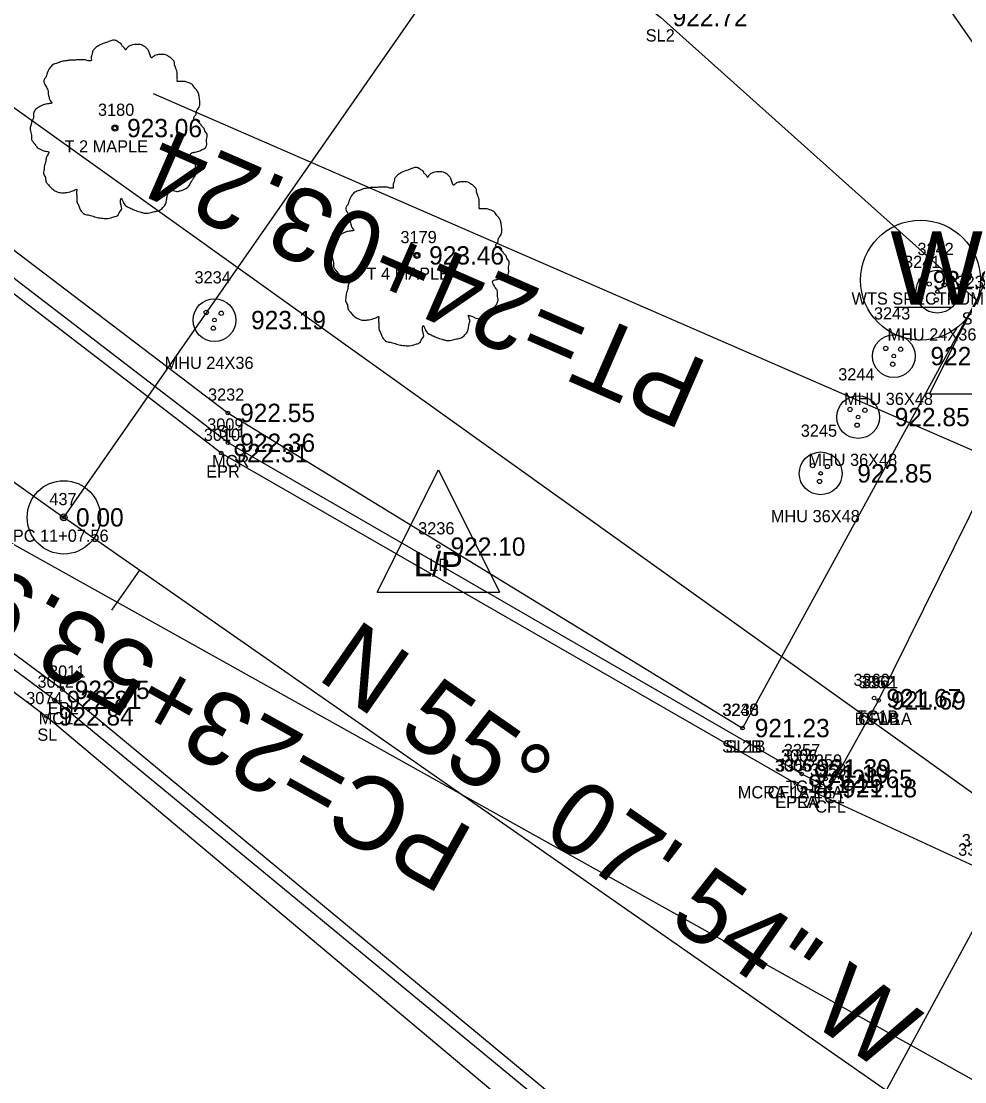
# Model space of a CAD drawing. Extents: x 1575382 to 1578175, y 1099175 to 1101955.
# Drawn here: x 1576997.2 to 1577074.4, y 1100781 to 1100867.9 of the extents above; entities that cross this region are included whole.
import ezdxf

# ---------------------------------------------------------------- set-up
doc = ezdxf.new("R2010")
doc.units = 0
for name, color, linetype in [('RD_EX_Conc', 7, 'Continuous'), ('RD_EX_Conc_txCode', 7, 'Continuous'), ('RD_EX_DR_Inlet', 7, 'Continuous'), ('RD_EX_DR_Pipe', 7, 'Continuous'), ('RD_EX_Road', 7, 'Continuous'), ('RD_EX_Road_txCode', 7, 'Continuous'), ('RD_EX_TX_Conc_ELEV', 7, 'Continuous'), ('RD_EX_TX_Road_ELEV', 7, 'Continuous'), ('RD_EX_TX_UT_ELEV', 7, 'Continuous'), ('RD_EX_TX_VEG_ELEV', 7, 'Continuous'), ('RD_EX_UT', 7, 'Continuous'), ('RD_EX_UT_txCode', 7, 'Continuous'), ('RD_EX_VEG', 7, 'Continuous'), ('RD_EX_VEG_txCode', 7, 'Continuous'), ('RD_HC_Cl', 7, 'Continuous'), ('RD_HC_Data', 7, 'Continuous'), ('RD_HC_Data_Tic', 7, 'Continuous'), ('RD_HC_Survey_ELEV', 7, 'Continuous'), ('RD_HC_txCode', 7, 'Continuous'), ('RD_SMD_Locator', 7, 'Continuous')]:
    doc.layers.add(name, color=color, linetype=linetype)

msp = doc.modelspace()

# ---------------------------------------------------------------- linework, layer by layer
at = {"layer": 'RD_EX_Conc'}
for points in [[(1577061.066, 1100806.234), (1577014.096, 1100833.352), (1576975.058, 1100863.303), (1576939.512, 1100897.242), (1576908.218, 1100933.822), (1576881.099, 1100974.578), (1576859.041, 1101017.292), (1576841.041, 1101063.527), (1576828.933, 1101110.765), (1576816.791, 1101158.901)], [(1577043.777, 1100776.098), (1576999.879, 1100812.296), (1576959.091, 1100842.628), (1576920.948, 1100878.726), (1576886.666, 1100919.361), (1576858.724, 1100961.136), (1576834.43, 1101008.647), (1576816.373, 1101055.231), (1576803.494, 1101104.71), (1576791.52, 1101152.573)], [(1577067.37, 1100812.254), (1577083.485, 1100844.878), (1577096.643, 1100874.508), (1577116.651, 1100919.942), (1577136.82, 1100965.443), (1577156.654, 1101010.405), (1577183.297, 1101070.643)], [(1577061.066, 1100806.234), (1577063.378, 1100805.064), (1577067.37, 1100812.254)]]:
    msp.add_lwpolyline(points, dxfattribs=at)
at = {"layer": 'RD_EX_DR_Inlet'}
for centre, radius in [((1577072.173, 1100845.722), 1.75), ((1577071.508, 1100846.352), 0.175), ((1577072.733, 1100846.282), 0.175), ((1577012.98, 1100843.399), 1.75), ((1577072.085, 1100845.058), 0.175), ((1577012.315, 1100844.029), 0.175), ((1577013.54, 1100843.959), 0.175), ((1577012.893, 1100842.734), 0.175), ((1577068.613, 1100840.447), 1.75), ((1577067.948, 1100841.076), 0.175), ((1577069.173, 1100841.007), 0.175), ((1577068.525, 1100839.782), 0.175), ((1577065.687, 1100835.457), 1.75), ((1577065.023, 1100836.086), 0.175), ((1577066.247, 1100836.017), 0.175), ((1577065.6, 1100834.792), 0.175), ((1577062.621, 1100830.846), 1.75), ((1577061.956, 1100831.476), 0.175), ((1577063.18, 1100831.406), 0.175), ((1577062.533, 1100830.181), 0.175)]:
    msp.add_circle(centre, radius, dxfattribs=at)
at = {"layer": 'RD_EX_DR_Pipe'}
msp.add_line((1577132.688, 1100782.794), (1577050.186, 1100902.125), dxfattribs=at)
at = {"layer": 'RD_EX_Road'}
for points in [[(1577060.606, 1100805.432), (1577013.537, 1100832.507), (1576974.41, 1100862.521), (1576938.821, 1100896.441), (1576907.275, 1100933.28), (1576880.287, 1100973.975), (1576858.202, 1101016.828), (1576840.123, 1101063.131), (1576827.927, 1101110.583), (1576815.842, 1101158.489)], [(1577060.606, 1100805.432), (1577075.531, 1100798.536), (1577081.931, 1100797.671), (1577087.923, 1100798.374), (1577091.212, 1100799.398), (1577094.487, 1100804.268), (1577106.896, 1100832.158), (1577119.895, 1100862.619), (1577139.857, 1100909.397), (1577159.206, 1100954.774), (1577178.498, 1100999.731), (1577192.432, 1101032.313), (1577206.431, 1101064.716)], [(1576898.125, 1100449.597), (1576900.298, 1100453.323), (1576908.44, 1100470.191), (1576911.626, 1100476.811), (1576915.143, 1100482.86), (1576932.491, 1100514.031), (1576964.319, 1100571.231), (1576981.085, 1100601.291), (1577005.143, 1100644.548), (1577029.514, 1100688.699), (1577055.929, 1100735.941), (1577058.213, 1100744.654), (1577059.154, 1100754.07), (1577057.45, 1100760.722), (1577053.131, 1100767.877), (1577044.533, 1100776.687), (1577044.533, 1100776.687), (1577000.541, 1100813.123), (1576959.676, 1100843.401), (1576921.642, 1100879.474), (1576887.689, 1100919.798), (1576859.542, 1100961.835), (1576835.397, 1101008.919), (1576817.257, 1101055.711)]]:
    msp.add_lwpolyline(points, dxfattribs=at)
at = {"layer": 'RD_EX_UT'}
for p, q in [((1577071.545, 1100837.363), (1577076.545, 1100847.363)), ((1577068.665, 1100844.456), (1577073.295, 1100844.456)), ((1577071.545, 1100837.363), (1577081.545, 1100837.363)), ((1577026.316, 1100821.125), (1577031.316, 1100831.125)), ((1577031.316, 1100831.125), (1577036.316, 1100821.125)), ((1577026.316, 1100821.125), (1577036.316, 1100821.125))]:
    msp.add_line(p, q, dxfattribs=at)
msp.add_lwpolyline([(1576697.982, 1101074.318), (1577079.486, 1100801.524), (1576931.929, 1100529.296), (1577183.503, 1100413.666)], dxfattribs=at)
msp.add_circle((1577070.794, 1100846.664), 4.908, dxfattribs=at)
at = {"layer": 'RD_EX_VEG'}
for points in [[(1576842.661, 1101165.203), (1576856.324, 1101117.296), (1576901.07, 1101050.702), (1576926.345, 1101005.763), (1576957.585, 1100975.469), (1576985.787, 1100943.994), (1577005.951, 1100901.315), (1577049.501, 1100868.209), (1577075.374, 1100845.032), (1577056.225, 1100809.989)], [(1576823.907, 1101161.244), (1576835.181, 1101111.009), (1576847.368, 1101072.746), (1576888.665, 1101041.707), (1576913.762, 1100995.867), (1576945.147, 1100967.302), (1576973.299, 1100933.425), (1576973.63, 1100896.298), (1576975.024, 1100865.506), (1577014.084, 1100835.799), (1577056.225, 1100809.989)], [(1576815.034, 1101055.099), (1576833.721, 1101006.581), (1576857.566, 1100960.375), (1576886.692, 1100916.883), (1576920.078, 1100877.681), (1576958.628, 1100841.518), (1576999.237, 1100810.946), (1577044.614, 1100772.82), (1577027.667, 1100742.339), (1577009.85, 1100750.508), (1576988.317, 1100759.291), (1576965.743, 1100773.629), (1576933.976, 1100810.235), (1576917.815, 1100828.049), (1576903.899, 1100864.233), (1576883.403, 1100895.406), (1576864.834, 1100917.249), (1576817.517, 1100956.766)]]:
    msp.add_lwpolyline(points, dxfattribs=at)
for centre, radius in [((1577004.83, 1100859.122), 0.25), ((1577004.818, 1100859.103), 0.0001), ((1577029.559, 1100848.695), 0.25), ((1577029.546, 1100848.676), 0.0001)]:
    msp.add_circle(centre, radius, dxfattribs=at)
for points in [[(1577004.962, 1100866.289), (1577004.662, 1100866.314), (1577004.338, 1100866.214), (1577004.088, 1100866.114), (1577003.863, 1100866.039), (1577003.638, 1100865.939), (1577003.338, 1100865.764), (1577003.113, 1100865.564), (1577002.988, 1100865.314), (1577002.938, 1100865.089), (1577002.888, 1100864.814), (1577002.888, 1100864.639), (1577002.763, 1100864.614), (1577002.613, 1100864.639), (1577002.363, 1100864.714), (1577002.113, 1100864.714), (1577001.864, 1100864.714), (1577001.514, 1100864.689), (1577001.164, 1100864.689), (1577000.889, 1100864.639), (1577000.564, 1100864.59), (1577000.189, 1100864.465), (1576999.839, 1100864.34), (1576999.54, 1100864.09), (1576999.29, 1100863.615), (1576999.165, 1100863.265), (1576999.015, 1100863.015), (1576999.165, 1100862.565), (1576999.34, 1100862.215), (1576999.365, 1100862.016), (1576999.44, 1100861.591), (1576999.54, 1100861.366), (1576999.665, 1100861.166), (1576999.59, 1100861.141), (1576999.215, 1100861.091), (1576998.915, 1100860.991), (1576998.49, 1100860.766), (1576998.265, 1100860.541), (1576998.165, 1100860.216), (1576998.14, 1100859.867), (1576998.04, 1100859.667), (1576997.965, 1100859.392), (1576997.94, 1100859.317), (1576997.89, 1100858.992), (1576997.99, 1100858.542), (1576998.015, 1100858.192), (1576998.14, 1100857.967), (1576998.29, 1100857.792), (1576998.465, 1100857.543), (1576998.865, 1100857.318), (1576999.19, 1100857.218), (1576999.39, 1100857.193), (1576999.215, 1100856.693), (1576999.165, 1100856.343), (1576999.04, 1100855.943), (1576999.04, 1100855.868), (1576998.99, 1100855.394), (1576999.14, 1100855.069), (1576999.215, 1100854.694), (1576999.39, 1100854.469), (1576999.665, 1100854.169), (1576999.989, 1100853.944), (1577000.489, 1100853.819), (1577000.889, 1100853.844), (1577001.464, 1100854.019), (1577001.714, 1100854.094), (1577001.689, 1100853.919), (1577001.714, 1100853.544), (1577001.714, 1100853.12), (1577001.864, 1100852.795), (1577001.964, 1100852.52), (1577002.113, 1100852.27), (1577002.438, 1100852.045), (1577002.838, 1100851.97), (1577003.263, 1100851.82), (1577003.713, 1100851.745), (1577004.213, 1100851.72), (1577004.812, 1100851.87), (1577005.087, 1100851.995), (1577005.187, 1100852.17), (1577005.387, 1100852.545), (1577005.337, 1100852.77), (1577005.362, 1100853.369), (1577005.462, 1100853.194), (1577005.637, 1100852.845), (1577006.137, 1100852.545), (1577006.537, 1100852.37), (1577007.011, 1100852.22), (1577007.311, 1100852.145), (1577007.786, 1100852.22), (1577008.161, 1100852.295), (1577008.536, 1100852.42), (1577008.836, 1100852.695), (1577009.01, 1100852.97), (1577009.06, 1100853.244), (1577009.135, 1100853.619), (1577009.185, 1100853.794)], [(1577009.185, 1100853.794), (1577009.11, 1100853.969), (1577009.06, 1100854.219), (1577009.135, 1100854.194), (1577009.31, 1100854.144), (1577009.585, 1100854.019), (1577009.81, 1100853.944), (1577010.135, 1100853.969), (1577010.41, 1100854.069), (1577010.86, 1100854.344), (1577011.135, 1100854.819), (1577011.409, 1100855.219), (1577011.484, 1100855.543), (1577011.434, 1100855.768), (1577011.409, 1100856.268), (1577011.209, 1100856.518), (1577011.159, 1100856.643), (1577011.06, 1100857.043), (1577011.135, 1100857.093), (1577011.409, 1100857.143), (1577011.784, 1100857.268), (1577012.059, 1100857.393), (1577012.284, 1100857.568), (1577012.359, 1100857.792), (1577012.334, 1100858.192), (1577012.384, 1100858.592), (1577012.309, 1100858.742), (1577012.209, 1100858.892), (1577012.134, 1100859.092), (1577011.984, 1100859.242), (1577011.884, 1100859.392), (1577011.784, 1100859.492), (1577011.659, 1100859.642), (1577011.484, 1100859.767), (1577011.334, 1100859.817), (1577011.284, 1100859.967), (1577011.434, 1100860.166), (1577011.484, 1100860.266), (1577011.509, 1100860.491), (1577011.734, 1100860.841), (1577011.784, 1100861.241), (1577011.734, 1100861.666), (1577011.684, 1100861.941), (1577011.534, 1100862.215), (1577011.334, 1100862.465), (1577011.209, 1100862.64), (1577011.035, 1100862.765), (1577010.71, 1100862.89), (1577010.46, 1100862.94), (1577010.11, 1100862.94), (1577009.91, 1100862.99), (1577009.935, 1100863.04), (1577009.935, 1100863.19), (1577009.935, 1100863.465), (1577009.86, 1100863.915), (1577009.71, 1100864.415), (1577009.71, 1100864.44), (1577009.61, 1100864.689), (1577009.385, 1100864.889), (1577009.21, 1100864.989), (1577009.01, 1100865.114), (1577008.761, 1100865.139), (1577008.461, 1100865.139), (1577008.186, 1100865.089), (1577007.986, 1100864.989), (1577007.811, 1100864.864), (1577007.736, 1100865.014), (1577007.636, 1100865.314), (1577007.586, 1100865.464), (1577007.436, 1100865.639), (1577007.211, 1100865.839), (1577006.761, 1100865.964), (1577006.137, 1100865.889), (1577005.837, 1100865.689), (1577005.687, 1100865.514), (1577005.637, 1100865.639), (1577005.437, 1100865.839), (1577005.337, 1100866.014), (1577005.162, 1100866.139), (1577005.012, 1100866.239), (1577004.912, 1100866.289)], [(1577029.691, 1100855.862), (1577029.391, 1100855.887), (1577029.066, 1100855.787), (1577028.816, 1100855.687), (1577028.591, 1100855.612), (1577028.366, 1100855.512), (1577028.066, 1100855.337), (1577027.841, 1100855.137), (1577027.716, 1100854.887), (1577027.666, 1100854.663), (1577027.616, 1100854.388), (1577027.616, 1100854.213), (1577027.492, 1100854.188), (1577027.342, 1100854.213), (1577027.092, 1100854.288), (1577026.842, 1100854.288), (1577026.592, 1100854.288), (1577026.242, 1100854.263), (1577025.892, 1100854.263), (1577025.617, 1100854.213), (1577025.292, 1100854.163), (1577024.918, 1100854.038), (1577024.568, 1100853.913), (1577024.268, 1100853.663), (1577024.018, 1100853.188), (1577023.893, 1100852.838), (1577023.743, 1100852.588), (1577023.893, 1100852.139), (1577024.068, 1100851.789), (1577024.093, 1100851.589), (1577024.168, 1100851.164), (1577024.268, 1100850.939), (1577024.393, 1100850.739), (1577024.318, 1100850.714), (1577023.943, 1100850.664), (1577023.643, 1100850.564), (1577023.218, 1100850.339), (1577022.993, 1100850.115), (1577022.893, 1100849.79), (1577022.869, 1100849.44), (1577022.769, 1100849.24), (1577022.694, 1100848.965), (1577022.669, 1100848.89), (1577022.619, 1100848.565), (1577022.719, 1100848.115), (1577022.744, 1100847.766), (1577022.869, 1100847.541), (1577023.018, 1100847.366), (1577023.193, 1100847.116), (1577023.593, 1100846.891), (1577023.918, 1100846.791), (1577024.118, 1100846.766), (1577023.943, 1100846.266), (1577023.893, 1100845.916), (1577023.768, 1100845.517), (1577023.768, 1100845.442), (1577023.718, 1100844.967), (1577023.868, 1100844.642), (1577023.943, 1100844.267), (1577024.118, 1100844.042), (1577024.393, 1100843.742), (1577024.718, 1100843.517), (1577025.218, 1100843.392), (1577025.617, 1100843.417), (1577026.192, 1100843.592), (1577026.442, 1100843.667), (1577026.417, 1100843.492), (1577026.442, 1100843.118), (1577026.442, 1100842.693), (1577026.592, 1100842.368), (1577026.692, 1100842.093), (1577026.842, 1100841.843), (1577027.167, 1100841.618), (1577027.566, 1100841.543), (1577027.991, 1100841.393), (1577028.441, 1100841.318), (1577028.941, 1100841.293), (1577029.541, 1100841.443), (1577029.815, 1100841.568), (1577029.915, 1100841.743), (1577030.115, 1100842.118), (1577030.065, 1100842.343), (1577030.09, 1100842.943), (1577030.19, 1100842.768), (1577030.365, 1100842.418), (1577030.865, 1100842.118), (1577031.265, 1100841.943), (1577031.74, 1100841.793), (1577032.04, 1100841.718), (1577032.514, 1100841.793), (1577032.889, 1100841.868), (1577033.264, 1100841.993), (1577033.564, 1100842.268), (1577033.739, 1100842.543), (1577033.789, 1100842.818), (1577033.864, 1100843.193), (1577033.914, 1100843.367)], [(1577033.914, 1100843.367), (1577033.839, 1100843.542), (1577033.789, 1100843.792), (1577033.864, 1100843.767), (1577034.039, 1100843.717), (1577034.314, 1100843.592), (1577034.538, 1100843.517), (1577034.863, 1100843.542), (1577035.138, 1100843.642), (1577035.588, 1100843.917), (1577035.863, 1100844.392), (1577036.138, 1100844.792), (1577036.213, 1100845.117), (1577036.163, 1100845.342), (1577036.138, 1100845.841), (1577035.938, 1100846.091), (1577035.888, 1100846.216), (1577035.788, 1100846.616), (1577035.863, 1100846.666), (1577036.138, 1100846.716), (1577036.513, 1100846.841), (1577036.787, 1100846.966), (1577037.012, 1100847.141), (1577037.087, 1100847.366), (1577037.062, 1100847.766), (1577037.112, 1100848.165), (1577037.037, 1100848.315), (1577036.937, 1100848.465), (1577036.862, 1100848.665), (1577036.712, 1100848.815), (1577036.613, 1100848.965), (1577036.513, 1100849.065), (1577036.388, 1100849.215), (1577036.213, 1100849.34), (1577036.063, 1100849.39), (1577036.013, 1100849.54), (1577036.163, 1100849.74), (1577036.213, 1100849.84), (1577036.238, 1100850.065), (1577036.463, 1100850.414), (1577036.513, 1100850.814), (1577036.463, 1100851.239), (1577036.413, 1100851.514), (1577036.263, 1100851.789), (1577036.063, 1100852.039), (1577035.938, 1100852.214), (1577035.763, 1100852.339), (1577035.438, 1100852.464), (1577035.188, 1100852.513), (1577034.838, 1100852.513), (1577034.638, 1100852.563), (1577034.663, 1100852.613), (1577034.663, 1100852.763), (1577034.663, 1100853.038), (1577034.588, 1100853.488), (1577034.438, 1100853.988), (1577034.438, 1100854.013), (1577034.338, 1100854.263), (1577034.114, 1100854.463), (1577033.939, 1100854.563), (1577033.739, 1100854.688), (1577033.489, 1100854.713), (1577033.189, 1100854.713), (1577032.914, 1100854.663), (1577032.714, 1100854.563), (1577032.539, 1100854.438), (1577032.464, 1100854.588), (1577032.364, 1100854.887), (1577032.314, 1100855.037), (1577032.164, 1100855.212), (1577031.94, 1100855.412), (1577031.49, 1100855.537), (1577030.865, 1100855.462), (1577030.565, 1100855.262), (1577030.415, 1100855.087), (1577030.365, 1100855.212), (1577030.165, 1100855.412), (1577030.065, 1100855.587), (1577029.89, 1100855.712), (1577029.741, 1100855.812), (1577029.641, 1100855.862)]]:
    msp.add_spline(points, degree=3, dxfattribs=at)
at = {"layer": 'RD_HC_Cl'}
msp.add_line((1577088.898, 1100765.75), (1577000.647, 1100827.242), dxfattribs=at)
msp.add_arc((1577257.909, 1101196.452), 450, 194.10128, 235.13175, dxfattribs=at)
at = {"layer": 'RD_HC_Data'}
for p, q in [((1577000.647, 1100827.242), (1577067.498, 1100923.183)), ((1577114.032, 1100815.757), (1577007.98, 1100861.919)), ((1577092.181, 1100771.631), (1576990.287, 1100828.5))]:
    msp.add_line(p, q, dxfattribs=at)
for radius in [3, 0.282]:
    msp.add_circle((1577000.647, 1100827.242), radius, dxfattribs=at)
at = {"layer": 'RD_HC_Data_Tic'}
msp.add_line((1577006.851, 1100822.919), (1577004.565, 1100819.637), dxfattribs=at)
at = {"layer": 'RD_SMD_Locator'}
for centre in [(1577004.83, 1100859.121), (1577029.559, 1100848.695), (1577070.794, 1100846.664), (1577072.173, 1100845.722), (1577012.98, 1100843.399), (1577068.613, 1100840.447), (1577014.084, 1100835.799), (1577065.687, 1100835.457), (1577014.096, 1100833.352), (1577013.537, 1100832.507), (1577062.621, 1100830.846), (1577000.647, 1100827.242), (1577031.316, 1100824.85), (1576999.879, 1100812.296), (1577000.541, 1100813.123), (1577067, 1100812.439), (1577067.37, 1100812.254), (1577067.37, 1100812.254), (1576999.237, 1100810.946), (1577056.225, 1100809.989), (1577056.225, 1100809.989), (1577061.066, 1100806.234), (1577061.066, 1100806.234), (1577061.237, 1100806.69), (1577060.606, 1100805.432), (1577060.606, 1100805.432), (1577063.034, 1100805.832), (1577063.378, 1100805.064)]:
    msp.add_circle(centre, 0.15, dxfattribs=at)

# ---------------------------------------------------------------- texts
at = {"layer": 'RD_EX_Conc_txCode'}
for s, p in [('3009', (1577012.388, 1100834.352)), ('MCR', (1577012.781, 1100831.352)), ('3012', (1576998.493, 1100813.296)), ('3360', (1577065.307, 1100813.439)), ('3362', (1577065.717, 1100813.254)), ('3361', (1577066, 1100813.254)), ('MCL', (1576998.587, 1100810.296)), ('BSW1A', (1577065.402, 1100810.254)), ('TC1B', (1577065.567, 1100810.439)), ('CFLB', (1577065.693, 1100810.254)), ('3005', (1577059.357, 1100807.234)), ('3356', (1577059.412, 1100807.234)), ('3357', (1577059.607, 1100807.69)), ('3359', (1577061.404, 1100806.832)), ('3358', (1577061.748, 1100806.064)), ('TC1A', (1577059.788, 1100804.69)), ('MCRA 12 FLAT', (1577055.838, 1100804.234)), ('CFLA 18', (1577058.271, 1100804.234)), ('TC1', (1577062.074, 1100803.832)), ('CFL', (1577062.173, 1100803.064)), ('3367', (1577074.183, 1100800.311))]:
    msp.add_text(s, height=1, dxfattribs=at).set_placement(p)
at = {"layer": 'RD_EX_Road_txCode'}
for s, p in [('3010', (1577012.112, 1100833.507)), ('EPR', (1577012.309, 1100830.507)), ('3011', (1576999.438, 1100814.123)), ('EPL', (1576999.336, 1100811.123)), ('3006', (1577058.874, 1100806.432)), ('3355', (1577058.976, 1100806.432)), ('EPRA', (1577058.889, 1100803.432)), ('EPLA', (1577058.913, 1100803.432)), ('3368', (1577073.878, 1100799.536))]:
    msp.add_text(s, height=1, dxfattribs=at).set_placement(p)
at = {"layer": 'RD_EX_TX_Conc_ELEV'}
for s, p in [('922.36', (1577015.096, 1100832.602)), ('922.81', (1577000.879, 1100811.546)), ('921.67', (1577068, 1100811.689)), ('921.69', (1577068.37, 1100811.504)), ('921.69', (1577068.37, 1100811.504)), ('921.39', (1577062.237, 1100805.94)), ('921.19', (1577062.066, 1100805.484)), ('921.19', (1577062.066, 1100805.484)), ('921.65', (1577064.034, 1100805.082)), ('921.18', (1577064.378, 1100804.314))]:
    msp.add_text(s, height=1.5, dxfattribs=at).set_placement(p)
at = {"layer": 'RD_EX_TX_Road_ELEV'}
for s, p in [('922.31', (1577014.537, 1100831.757)), ('922.75', (1577001.541, 1100812.373)), ('921.19', (1577061.606, 1100804.682)), ('921.19', (1577061.606, 1100804.682))]:
    msp.add_text(s, height=1.5, dxfattribs=at).set_placement(p)
at = {"layer": 'RD_EX_TX_UT_ELEV'}
for s, p in [('922.91', (1577071.794, 1100845.914)), ('923.19', (1577015.98, 1100842.649)), ('922.92', (1577071.613, 1100839.697)), ('922.85', (1577068.687, 1100834.707)), ('922.85', (1577065.621, 1100830.096)), ('922.10', (1577032.316, 1100824.1))]:
    msp.add_text(s, height=1.5, dxfattribs=at).set_placement(p)
at = {"layer": 'RD_EX_TX_VEG_ELEV'}
for s, p in [('922.72', (1577050.501, 1100867.459)), ('923.06', (1577005.83, 1100858.371)), ('923.46', (1577030.559, 1100847.945)), ('922.55', (1577015.084, 1100835.049)), ('922.84', (1577000.237, 1100810.196)), ('921.23', (1577057.225, 1100809.239)), ('921.23', (1577057.225, 1100809.239))]:
    msp.add_text(s, height=1.5, dxfattribs=at).set_placement(p)
at = {"layer": 'RD_EX_UT'}
for s, height, p in [('W', 6, (1577068.329, 1100844.663)), ('L/P', 2, (1577029.307, 1100822.407))]:
    msp.add_text(s, height=height, dxfattribs=at).set_placement(p)
at = {"layer": 'RD_EX_UT_txCode'}
for s, p in [('3242', (1577070.543, 1100848.722)), ('3241', (1577069.447, 1100847.664)), ('3234', (1577011.35, 1100846.399)), ('WTS SPECTRUM', (1577065.148, 1100844.664)), ('3243', (1577066.983, 1100843.447)), ('MHU 24X36', (1577068.094, 1100841.722)), ('MHU 24X36', (1577008.901, 1100839.399)), ('3244', (1577064.057, 1100838.457)), ('MHU 36X48', (1577064.534, 1100836.447)), ('3245', (1577060.991, 1100833.846)), ('MHU 36X48', (1577061.608, 1100831.457)), ('MHU 36X48', (1577058.542, 1100826.846)), ('3236', (1577029.662, 1100825.85)), ('LP', (1577030.56, 1100822.85))]:
    msp.add_text(s, height=1, dxfattribs=at).set_placement(p)
at = {"layer": 'RD_EX_VEG_txCode'}
for s, p in [('SL2', (1577048.296, 1100866.209)), ('3180', (1577003.444, 1100860.121)), ('T 2 MAPLE', (1577000.708, 1100857.121)), ('3179', (1577028.212, 1100849.695)), ('T 4 MAPLE', (1577025.437, 1100846.695)), ('3237', (1577073.744, 1100846.032)), ('SL2', (1577074.169, 1100843.032)), ('3232', (1577012.454, 1100836.799)), ('SL1', (1577013.163, 1100833.799)), ('3074', (1576997.568, 1100811.946)), ('3240', (1577054.555, 1100810.989)), ('3238', (1577054.595, 1100810.989)), ('SL', (1576998.481, 1100808.946)), ('SL2B', (1577054.547, 1100807.989)), ('SL1B', (1577054.831, 1100807.989))]:
    msp.add_text(s, height=1, dxfattribs=at).set_placement(p)
at = {"layer": 'RD_HC_Data'}
for s, rotation, p in [('PT=24+03.24', 156.47772, (1577053.635, 1100839.865)), ('PC=23+53.98', 150.8329, (1577034.448, 1100801.562)), ('N 55%%d 07\' 54" W', 325.13175, (1577021.254, 1100814.102))]:
    msp.add_text(s, height=6, rotation=rotation, dxfattribs=at).set_placement(p)
at = {"layer": 'RD_HC_Survey_ELEV'}
msp.add_text('0.00', height=1.5, dxfattribs=at).set_placement((1577001.648, 1100826.492))
at = {"layer": 'RD_HC_txCode'}
for s, p in [('437', (1576999.466, 1100828.242)), ('PC 11+07.56', (1576996.474, 1100825.242))]:
    msp.add_text(s, height=1, dxfattribs=at).set_placement(p)

doc.saveas('drawing.dxf')
